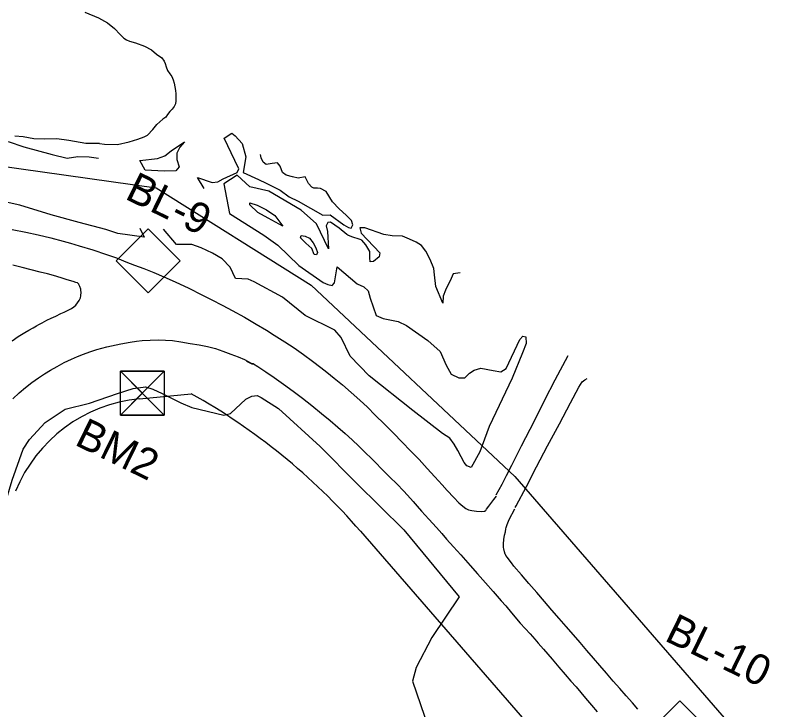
# Model space of a CAD drawing. Extents: x 1517485 to 1521905, y 636528 to 640355.
# Drawn here: x 1520887 to 1521396, y 638045 to 638500 of the extents above; entities that cross this region are included whole.
import ezdxf

# ---------------------------------------------------------------- set-up
doc = ezdxf.new("R2010")
doc.units = 0
for name, color, linetype in [('CTL Secondary Horizontal and Vertical Text', 7, 'Continuous'), ('CTL Vertical Benchmark CELL', 7, 'Continuous'), ('CTL Vertical Benchmark Text', 7, 'Continuous'), ('Default', 7, 'Continuous'), ('Exist Hydro Stream or Body of Water', 7, 'Continuous'), ('Exist Right of Way Line', 7, 'Continuous'), ('Exist Roads EOP', 7, 'Continuous'), ('Exist Roads EOP Other', 7, 'Continuous'), ('Exist Vegetation Woods Line', 7, 'Continuous')]:
    doc.layers.add(name, color=color, linetype=linetype)

msp = doc.modelspace()

# ---------------------------------------------------------------- linework, layer by layer
at = {"layer": 'CTL Vertical Benchmark CELL'}
msp.add_line((1520969.83, 638252.04), (1520969.83, 638252.04), dxfattribs=at)
msp.add_lwpolyline([(1520955.43, 638266.39), (1520984.18, 638266.39), (1520984.18, 638237.64), (1520955.43, 638237.64)], close=True, dxfattribs=at)
for points in [[(1520984.18, 638266.39), (1520955.43, 638237.64), (1520969.8, 638252.02), (1520984.18, 638237.64), (1520955.43, 638266.39)], [(1520969.8, 638252.02), (1520984.18, 638266.39), (1520955.43, 638266.39), (1520969.8, 638252.02)], [(1520969.8, 638252.02), (1520955.43, 638237.64), (1520984.18, 638237.64), (1520969.8, 638252.02)]]:
    msp.add_lwpolyline(points, dxfattribs=at)
at = {"layer": 'Default'}
msp.add_line((1520973.48, 638338.74), (1520973.48, 638338.74), dxfattribs=at)
for points in [[(1520952.62, 638338.81), (1520973.59, 638359.77), (1520994.59, 638338.77), (1520973.62, 638317.81)], [(1521301.41, 638029.25), (1521322.38, 638050.22), (1521343.38, 638029.22), (1521322.41, 638008.25)]]:
    msp.add_lwpolyline(points, close=True, dxfattribs=at)
at = {"layer": 'Exist Hydro Stream or Body of Water'}
for points in [[(1520932, 638501.95), (1520941, 638498.41), (1520946.98, 638494.99), (1520951.57, 638491.21)], [(1520951.57, 638491.21), (1520955.36, 638487.34), (1520957.67, 638484.97), (1520959.49, 638483.96), (1520961.29, 638483.08), (1520965.33, 638481.98), (1520971.31, 638479.66), (1520975.72, 638477.25), (1520979.08, 638474.5), (1520982.49, 638471.95), (1520984.11, 638469.94), (1520984.79, 638468.33), (1520985.38, 638466.09), (1520986.27, 638463.85), (1520987.93, 638461.54), (1520989.26, 638459.77), (1520990.06, 638457.7), (1520990.74, 638455.39), (1520991.19, 638453.1), (1520991.58, 638450.59), (1520991.67, 638448.38), (1520991.76, 638445.98), (1520991.79, 638443.74), (1520991.46, 638441.9), (1520990.58, 638440.12), (1520989.46, 638438.35), (1520987.77, 638436.76), (1520986.3, 638434.85), (1520985.15, 638433.19), (1520983.28, 638431.77)], [(1520941.65, 638415.83), (1520945, 638415.43), (1520953.45, 638415.29), (1520961.18, 638416.84), (1520966.88, 638418.75), (1520970.97, 638420.15), (1520973.2, 638421.35), (1520976.68, 638425.1), (1520979.22, 638428.37), (1520983.28, 638431.77)], [(1520941.65, 638415.83), (1520932.78, 638415.84), (1520921.69, 638417.8), (1520913.76, 638418.83), (1520905.42, 638418.78), (1520898.54, 638418.95), (1520891.56, 638420.25), (1520886.13, 638420.7)]]:
    msp.add_lwpolyline(points, dxfattribs=at)
at = {"layer": 'Exist Right of Way Line'}
for p, q in [((1520859.18, 638403.68), (1520978.8, 638386.68)), ((1520978.8, 638386.68), (1521080.53, 638322.97)), ((1521080.53, 638322.97), (1521214.06, 638197.45)), ((1520968, 638248.37), (1521001.92, 638251.65)), ((1521214.06, 638197.45), (1521416.61, 637964.14)), ((1521112.91, 638161.42), (1521340.77, 637898.96))]:
    msp.add_line(p, q, dxfattribs=at)
for centre, radius, start, end in [((1520799.53, 637889.35), 415, 40.9639, 60.8107), ((1520977.43, 638150.83), 98, 95.5211, 157.8844)]:
    msp.add_arc(centre, radius, start, end, dxfattribs=at)
at = {"layer": 'Exist Roads EOP'}
msp.add_line((1521038.05, 638273.12), (1521042.16, 638271.16), dxfattribs=at)
for points in [[(1520884.39, 638359.49), (1520893.43, 638357.62), (1520901.53, 638355.83), (1520909.8, 638353.88), (1520917.81, 638351.77), (1520922.7, 638350.39), (1520928.39, 638348.76), (1520937.43, 638346.01), (1520946.38, 638343.05), (1520952.82, 638340.78), (1520959.04, 638338.3), (1520964.62, 638336.06), (1520970.75, 638333.79), (1520977.27, 638331.22), (1520983.98, 638328.39), (1520991.31, 638325.13), (1521000.25, 638320.9), (1521008.79, 638316.67), (1521014.86, 638313.53), (1521022.6, 638309.49), (1521028.76, 638306.24), (1521036.85, 638301.81), (1521044.38, 638297.4), (1521051.28, 638293.27), (1521056.34, 638290.16), (1521063.31, 638285.74), (1521069.29, 638281.82), (1521075.51, 638277.44), (1521081.38, 638273), (1521086.8, 638268.87), (1521090.78, 638265.83), (1521095.7, 638261.93), (1521100.99, 638257.46), (1521106.75, 638252.41), (1521112.35, 638247.38), (1521117.39, 638242.75), (1521122.61, 638237.71), (1521128.66, 638231.77), (1521134.5, 638225.87), (1521140.32, 638219.85), (1521145.78, 638214.23), (1521151.3, 638208.46), (1521156.65, 638202.7), (1521161.68, 638197.11), (1521166.42, 638191.84), (1521169.64, 638188.29), (1521174.13, 638183.51), (1521177.49, 638180.03), (1521179.91, 638177.81), (1521181.89, 638176.38), (1521182.78, 638175.91), (1521183.71, 638175.55), (1521185.89, 638175), (1521188.9, 638174.62), (1521192.13, 638174.49), (1521193.9, 638174.54), (1521194.15, 638174.55), (1521194.48, 638174.61), (1521194.58, 638174.64), (1521194.68, 638174.69), (1521194.77, 638174.76), (1521195.07, 638175.11), (1521195.64, 638175.86), (1521197.06, 638177.81), (1521200.39, 638182.27), (1521202.02, 638184.39)], [(1520884.34, 638286.49), (1520888.38, 638289.15), (1520892.69, 638291.81), (1520895.4, 638293.36), (1520898.27, 638294.95), (1520900.42, 638296.23), (1520901.87, 638297.07), (1520904.13, 638298.26), (1520907.21, 638299.89), (1520909.9, 638301.2), (1520912.97, 638302.65), (1520916.36, 638304.24), (1520918.57, 638305.29), (1520921.17, 638306.55), (1520923.34, 638307.69), (1520924.91, 638308.68), (1520926.13, 638309.78), (1520927.34, 638311.21), (1520928.46, 638312.94), (1520929.11, 638314.22), (1520929.24, 638314.58), (1520929.45, 638315.98), (1520929.58, 638318.31), (1520929.53, 638319.4), (1520929.39, 638320.31), (1520928.89, 638321.97), (1520928.25, 638323.37), (1520928.09, 638323.63), (1520927.92, 638323.84), (1520927.75, 638324.02), (1520927.58, 638324.16), (1520927.19, 638324.37), (1520926.14, 638324.71), (1520924.34, 638325.28), (1520920.48, 638326.48), (1520916.59, 638327.67), (1520911.6, 638329.14), (1520907.54, 638330.26), (1520902.7, 638331.52), (1520896.86, 638332.97), (1520891.02, 638334.54), (1520884.89, 638336.02)], [(1520884.92, 638248.43), (1520889.04, 638252.22), (1520893.14, 638255.76), (1520897.27, 638259.04), (1520901.74, 638262.17), (1520905.55, 638264.69), (1520909.57, 638267.16), (1520913.85, 638269.58), (1520918.56, 638272.07), (1520923.32, 638274.4), (1520927.3, 638276.13), (1520931.23, 638277.66), (1520935.38, 638279.15), (1520939.96, 638280.63), (1520946.56, 638282.41), (1520955.7, 638284.41), (1520961.73, 638285.47), (1520966.04, 638286.06), (1520969.72, 638286.54), (1520974.95, 638286.9), (1520980.2, 638286.98), (1520984.89, 638286.91), (1520989.57, 638286.56), (1520995.14, 638285.7), (1521001.13, 638284.71), (1521007, 638283.7), (1521012.59, 638282.57), (1521017.79, 638281.26), (1521022.65, 638279.66), (1521027.91, 638277.69), (1521032.66, 638275.87), (1521036.71, 638274.09), (1521040.83, 638271.97), (1521041.72, 638271.55), (1521042.1, 638271.45), (1521042.25, 638271.42), (1521042.39, 638271.4), (1521042.63, 638271.33), (1521045.52, 638269.64), (1521050.79, 638266.14), (1521056.21, 638262.43), (1521062.31, 638258.05), (1521068.64, 638253.38), (1521074.81, 638248.76), (1521081.08, 638243.86), (1521087.28, 638238.78), (1521092.98, 638234.01), (1521098.04, 638229.75), (1521102.87, 638225.57), (1521107.5, 638221.36), (1521111.83, 638217.27), (1521116.02, 638213.22), (1521120.17, 638209.13), (1521123.08, 638206.09), (1521126.45, 638202.58), (1521128.77, 638200.2), (1521132.19, 638196.92), (1521136.65, 638192.51), (1521141.22, 638187.69), (1521145.66, 638182.9), (1521147.52, 638180.9), (1521150.07, 638177.97), (1521153.01, 638174.66), (1521157.81, 638169.29), (1521162.66, 638163.82), (1521166.14, 638159.9), (1521169.38, 638156.36), (1521173.9, 638151.31), (1521178.65, 638145.92), (1521181.72, 638142.52), (1521184.76, 638139.07), (1521189.7, 638133.47), (1521194.83, 638127.69), (1521200.01, 638121.83), (1521205.26, 638115.87), (1521208.23, 638112.41), (1521211.94, 638107.94), (1521217.7, 638101.15), (1521220.95, 638097.58), (1521224.11, 638094.07), (1521227.16, 638090.55), (1521229.46, 638087.91), (1521232.88, 638084.03), (1521238.51, 638077.49), (1521242.98, 638072.25), (1521247.09, 638067.44), (1521250.83, 638063.19), (1521254.34, 638059.27), (1521260.56, 638051.91), (1521264.32, 638047.38), (1521268.1, 638042.93)], [(1521294.79, 638044.65), (1521291.22, 638048.78), (1521287.2, 638053.39), (1521283, 638058.2), (1521278.66, 638063.19), (1521274.23, 638068.33), (1521269.9, 638073.34), (1521265.7, 638078.24), (1521261.41, 638083.24), (1521257.02, 638088.37), (1521252.5, 638093.58), (1521247.86, 638098.87), (1521243.18, 638104.25), (1521238.44, 638109.73), (1521233.53, 638115.39), (1521228.46, 638121.22), (1521223.34, 638127.1), (1521218.42, 638132.75), (1521213.54, 638138.49), (1521211.88, 638140.7), (1521210.48, 638142.64), (1521209.25, 638144.29), (1521208.27, 638145.63), (1521207.96, 638146.13), (1521207.87, 638146.33), (1521207.38, 638147.87), (1521206.87, 638149.92), (1521206.75, 638150.86), (1521206.73, 638153.15), (1521206.85, 638156.07), (1521207.28, 638158.86), (1521207.92, 638161.16), (1521208.15, 638162.99), (1521208.34, 638163.87), (1521209.07, 638165.97), (1521210.5, 638169.08), (1521214.1, 638176.21)]]:
    msp.add_lwpolyline(points, dxfattribs=at)
at = {"layer": 'Exist Roads EOP Other'}
for points in [[(1521201.82, 638185.32), (1521205.77, 638192.36), (1521208.64, 638198), (1521212.06, 638204.77), (1521218.48, 638217.48), (1521226.92, 638233.83), (1521233.74, 638247.59), (1521240.68, 638260.72), (1521249.14, 638276.71)], [(1521214.44, 638176.97), (1521214.98, 638178.06), (1521221.82, 638190.91), (1521228.29, 638203.68), (1521235.57, 638217.49), (1521243.35, 638231.94), (1521250.71, 638245.76), (1521256.03, 638255.94), (1521257.11, 638257.65), (1521258.39, 638259.43), (1521260.04, 638260.82), (1521261.5, 638261.73)]]:
    msp.add_lwpolyline(points, dxfattribs=at)
at = {"layer": 'Exist Vegetation Woods Line'}
for points in [[(1521010.4, 638386.43), (1521006.03, 638393.57), (1521015.52, 638390.24), (1521019.34, 638390.8), (1521022.78, 638392.69), (1521032, 638396.88), (1521033.18, 638399.25), (1521030.38, 638404.67), (1521023.37, 638419.36), (1521028.41, 638422.6), (1521030.75, 638420.99), (1521035.27, 638415.8), (1521037.6, 638407.2), (1521036.03, 638396.93), (1521046.01, 638392.33), (1521050.92, 638389.92), (1521060.23, 638385.14), (1521066, 638380.9), (1521071.99, 638377.96), (1521088.14, 638368.85)], [(1520881.75, 638417.1), (1520892.15, 638413.77), (1520910.69, 638408.61)], [(1520968.08, 638404.78), (1520979.82, 638406.07), (1520984.49, 638407.69), (1520988.73, 638411.15), (1520997.39, 638417.04), (1520994.43, 638413.44), (1520992.49, 638409.47), (1520992.54, 638405.27), (1520994.05, 638400.65), (1520991.86, 638397.92), (1520984.17, 638397.75), (1520971.63, 638398.44), (1520968.08, 638404.78)], [(1520910.69, 638408.61), (1520920.46, 638406.21), (1520927.53, 638407.4), (1520934.93, 638407.19), (1520941.09, 638406.19)], [(1521090.28, 638384.41), (1521086.61, 638386.22), (1521084.62, 638386.57), (1521082.27, 638386.62), (1521080.89, 638387.3), (1521078.73, 638389.52), (1521076.63, 638393.92), (1521072.08, 638393.21), (1521068.25, 638393.88), (1521064.04, 638395.1), (1521061.83, 638396.93), (1521060.29, 638401.06), (1521058.35, 638403.22), (1521055.04, 638402.68), (1521051.08, 638402.17), (1521048.96, 638403.5), (1521047.75, 638406.36), (1521047.37, 638408.68)], [(1521084.07, 638363.24), (1521074.03, 638372.03), (1521052.83, 638384.63), (1521040.23, 638387.36), (1521031.9, 638395.11), (1521023.33, 638389.31), (1521027.06, 638369.83), (1521049.6, 638355.64), (1521058.65, 638349.24), (1521072.49, 638335.77)], [(1521088.14, 638368.85), (1521092.99, 638369.13), (1521101.91, 638362.42), (1521104.99, 638360.82), (1521106.78, 638360.37), (1521107.76, 638362.46), (1521106.97, 638365.32), (1521103.5, 638368.92), (1521098.89, 638372.95), (1521094.43, 638377.56), (1521090.28, 638384.41)], [(1520968.07, 638360.24), (1520970.95, 638354.34), (1520953.68, 638356.7), (1520945.93, 638359.46), (1520928.43, 638364.09), (1520909.94, 638369.1), (1520889.49, 638375.43), (1520865.36, 638380.59)], [(1521062.03, 638361.61), (1521052.36, 638366.84), (1521045.45, 638370.56), (1521040.27, 638375.51), (1521040.29, 638376.98), (1521045.07, 638375.29), (1521051.27, 638372.24), (1521056.71, 638368.58), (1521062.03, 638361.61)], [(1521098.86, 638360.41), (1521093.12, 638364.22), (1521091.5, 638363.99), (1521090.32, 638361.94), (1521091.16, 638358.05), (1521091.87, 638346.66), (1521084.07, 638363.24)], [(1521061.68, 638315.07), (1521043.11, 638325.04), (1521039.32, 638326.84), (1521031.01, 638327.3), (1521027.45, 638334.73), (1521022.13, 638340.27), (1521015.86, 638343.8), (1521008.47, 638347.43), (1521002.36, 638349.61), (1520992.18, 638349.63), (1520983.62, 638359.54)], [(1521103.95, 638356.24), (1521098.86, 638360.41)], [(1521178.32, 638331.03), (1521173.67, 638330.26), (1521172.29, 638327.28), (1521168.72, 638319.62), (1521167.2, 638315.71), (1521166.92, 638311.03), (1521162.32, 638321.93), (1521161.36, 638329.76), (1521160.96, 638333.9), (1521158.67, 638339.77), (1521155.85, 638345.25), (1521152.84, 638348.86), (1521149.35, 638351.21), (1521145.12, 638353.18), (1521140.46, 638355.12), (1521133.67, 638355.27), (1521128.2, 638356.09), (1521115.75, 638360.52), (1521112.47, 638360.46), (1521113.25, 638356.99), (1521125.48, 638344.17), (1521125.15, 638341.5), (1521121.46, 638338.46), (1521119.18, 638338.15), (1521119.07, 638340.77), (1521118.95, 638344.9), (1521116.49, 638349.33), (1521113.77, 638352.36), (1521112.78, 638352.82), (1521107.22, 638354.63), (1521104.54, 638355.75), (1521103.95, 638356.24)], [(1521082.59, 638342.94), (1521080.89, 638346.99), (1521077.03, 638350.43), (1521073.46, 638353.94), (1521073.87, 638355.5), (1521076.69, 638355.06), (1521079.53, 638353.69), (1521081.75, 638350.76), (1521083.49, 638347.45), (1521084.6, 638344.32), (1521083.93, 638342.85), (1521082.59, 638342.94)], [(1521072.49, 638335.77), (1521088.39, 638324.7), (1521091.52, 638323.24), (1521094.25, 638322.62), (1521095.89, 638324.37), (1521097.59, 638335.03), (1521110.81, 638323.73), (1521115.12, 638321.72), (1521117.87, 638319.1), (1521119.23, 638314.3), (1521123.25, 638303.09), (1521127.66, 638301.04), (1521137.67, 638299.01), (1521143.12, 638296.51), (1521156.97, 638286.61), (1521165.21, 638279.46), (1521169.04, 638270.52), (1521172.32, 638264.53), (1521177.38, 638262.04), (1521181.22, 638262.02), (1521184.39, 638265.07), (1521187.52, 638267.19), (1521191.76, 638268.43), (1521199.9, 638266.89), (1521204.91, 638266.12), (1521208.49, 638268.12), (1521217.35, 638287.17), (1521219.31, 638289.54), (1521221.27, 638288.92), (1521221.6, 638284.71), (1521219.05, 638278.52), (1521212.41, 638261.89), (1521197.18, 638230.2), (1521191.14, 638213.65), (1521185.54, 638203.27)], [(1521185.54, 638203.27), (1521182.63, 638204.3), (1521180.96, 638206.62), (1521178.92, 638210.35), (1521176.75, 638214.39), (1521174.28, 638218.49), (1521171.48, 638222.49), (1521166.76, 638225.68), (1521147.23, 638240.77), (1521118.67, 638263.34), (1521106.03, 638276.26), (1521100.32, 638288.48), (1521096.12, 638293.36), (1521076.54, 638303.07), (1521061.68, 638315.07)], [(1520775.44, 638043.96), (1520800.09, 638057.16), (1520811.71, 638065.52), (1520824.19, 638077.3), (1520841.4, 638098.42), (1520851.2, 638114.29), (1520859.95, 638130.31), (1520868.44, 638150.4), (1520877.35, 638171.36), (1520884.38, 638195.02), (1520891.61, 638215.25), (1520895.85, 638221.65), (1520906.1, 638232.7), (1520919.29, 638241.61), (1520935.14, 638245.55), (1520953.48, 638251.83), (1520963.71, 638255.09), (1520971.81, 638256.14), (1520976.73, 638254.73), (1520982.78, 638251.76), (1520988.6, 638248.9), (1520995.05, 638245.75), (1521002.19, 638242.73), (1521023.27, 638237.65)], [(1521023.27, 638237.65), (1521027.53, 638238.78), (1521037.79, 638248.11), (1521041.64, 638250.04), (1521045.03, 638250.51), (1521047.81, 638249.23), (1521059.01, 638241.9), (1521086.39, 638217.04), (1521110.27, 638193.05), (1521141.42, 638162.39), (1521177.5, 638118.31), (1521159.76, 638091.69), (1521149.47, 638072.15), (1521146.91, 638063.11), (1521157.39, 638032.39), (1521142.19, 638029.15), (1521137.39, 638026.58), (1521135.84, 638022.99), (1521137.75, 638017.23), (1521141.04, 637991.7), (1521150, 637972.66), (1521174.05, 637939.4), (1521179.02, 637927.94), (1521183.89, 637905.13)]]:
    msp.add_lwpolyline(points, dxfattribs=at)

# ---------------------------------------------------------------- texts
at = {"layer": 'CTL Secondary Horizontal and Vertical Text'}
for s, p in [('BL-9', (1520957.66, 638379.87)), ('BL-10', (1521311.56, 638090.08))]:
    msp.add_text(s, height=20, rotation=333.9377, dxfattribs=at).set_placement(p)
at = {"layer": 'CTL Vertical Benchmark Text'}
msp.add_text('BM2', height=20, rotation=333.9377, dxfattribs=at).set_placement((1520924.66, 638218.47))

doc.saveas('drawing.dxf')
